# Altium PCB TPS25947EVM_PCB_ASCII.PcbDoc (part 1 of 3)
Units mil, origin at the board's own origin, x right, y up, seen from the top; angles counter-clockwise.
Board outline 6500 x 3000 mil, 4 copper layers (L1-Top Layer, L2-GND1, L3-PWR/SIG, L4-Bottom Layer), stack 63.4 mil thick; 232 components, 92 nets, 448 pads, 577 vias.
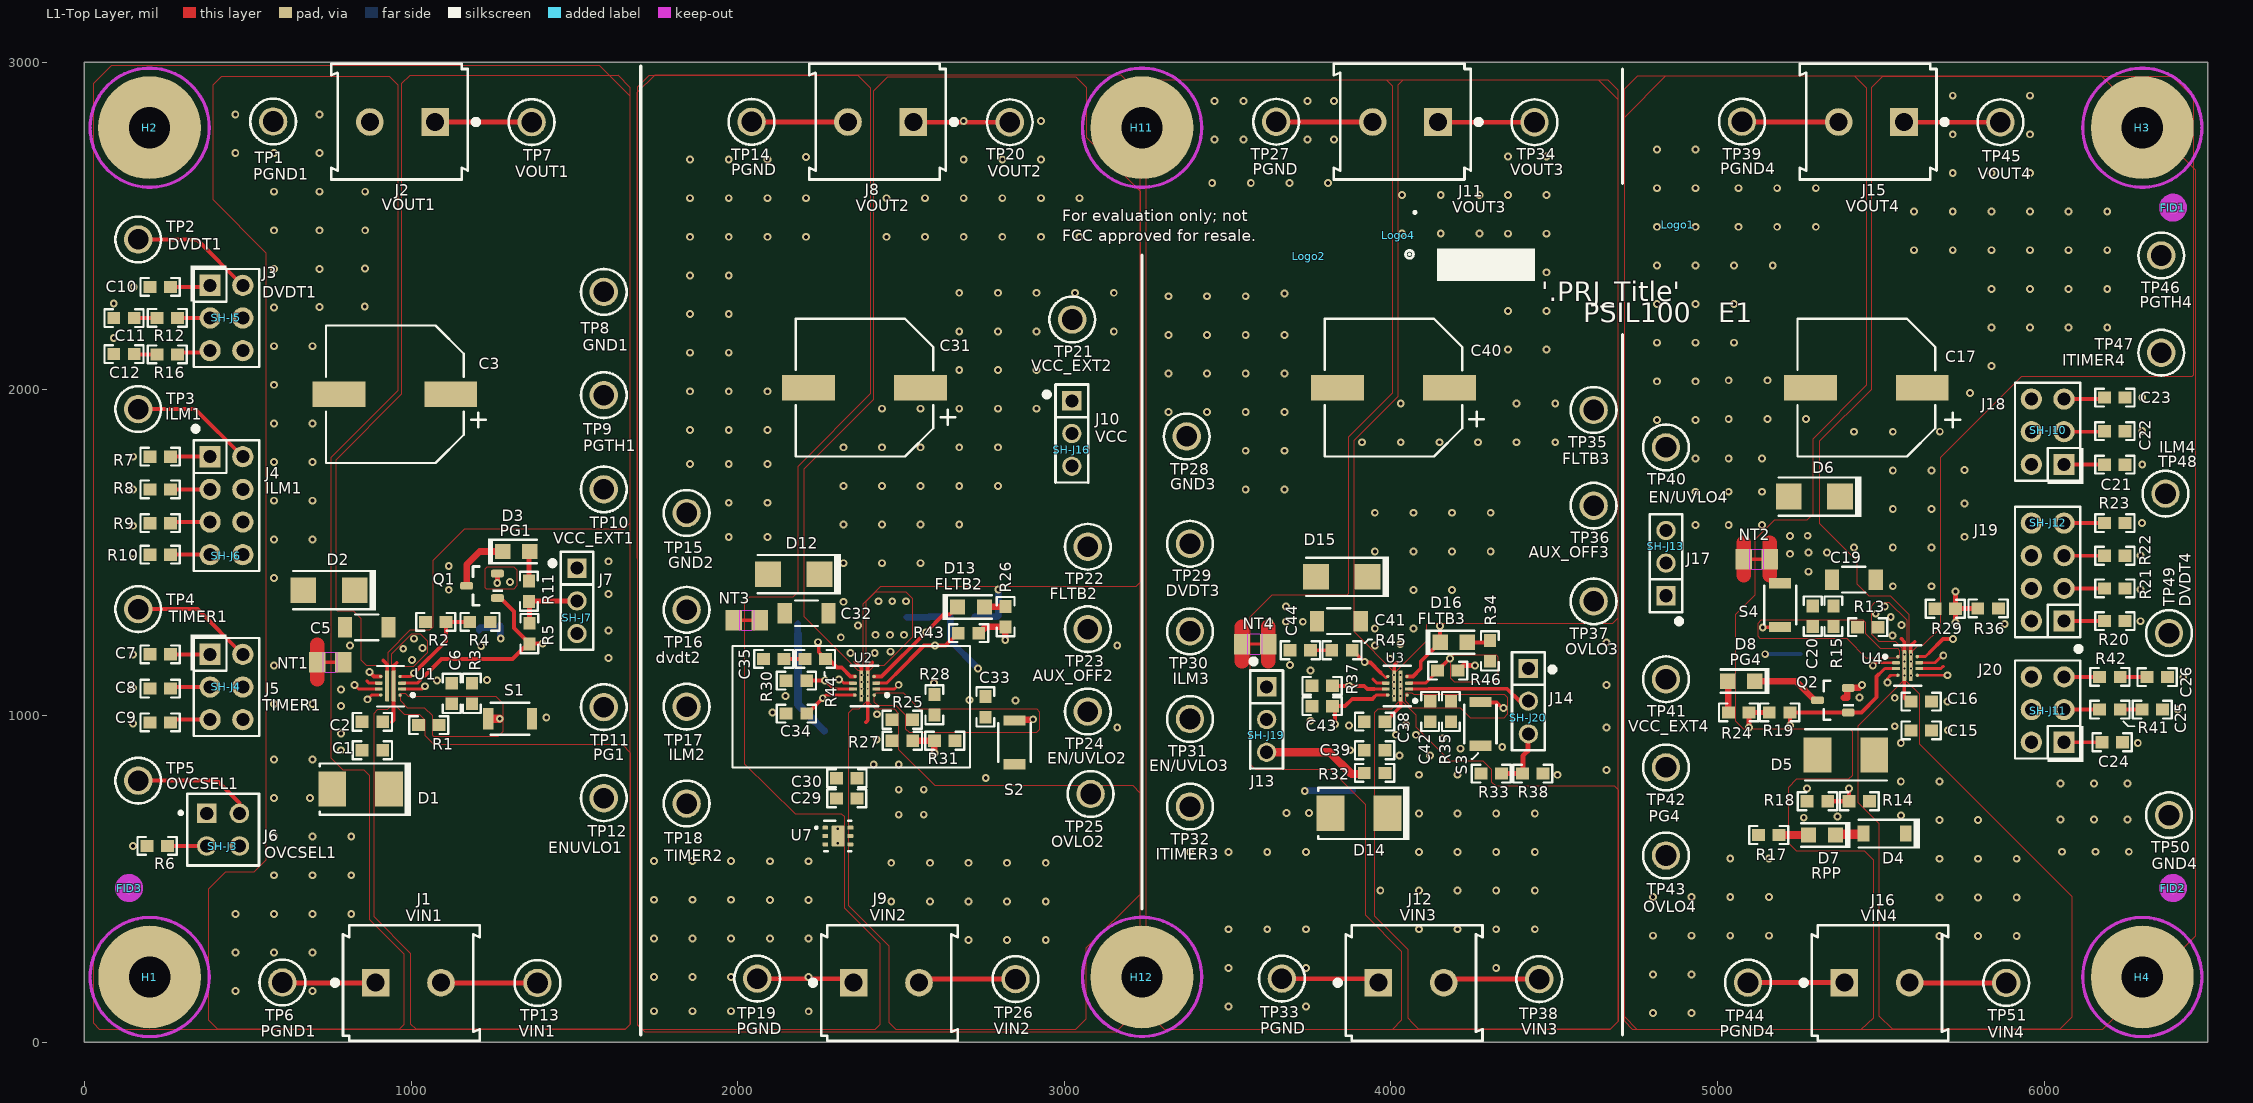
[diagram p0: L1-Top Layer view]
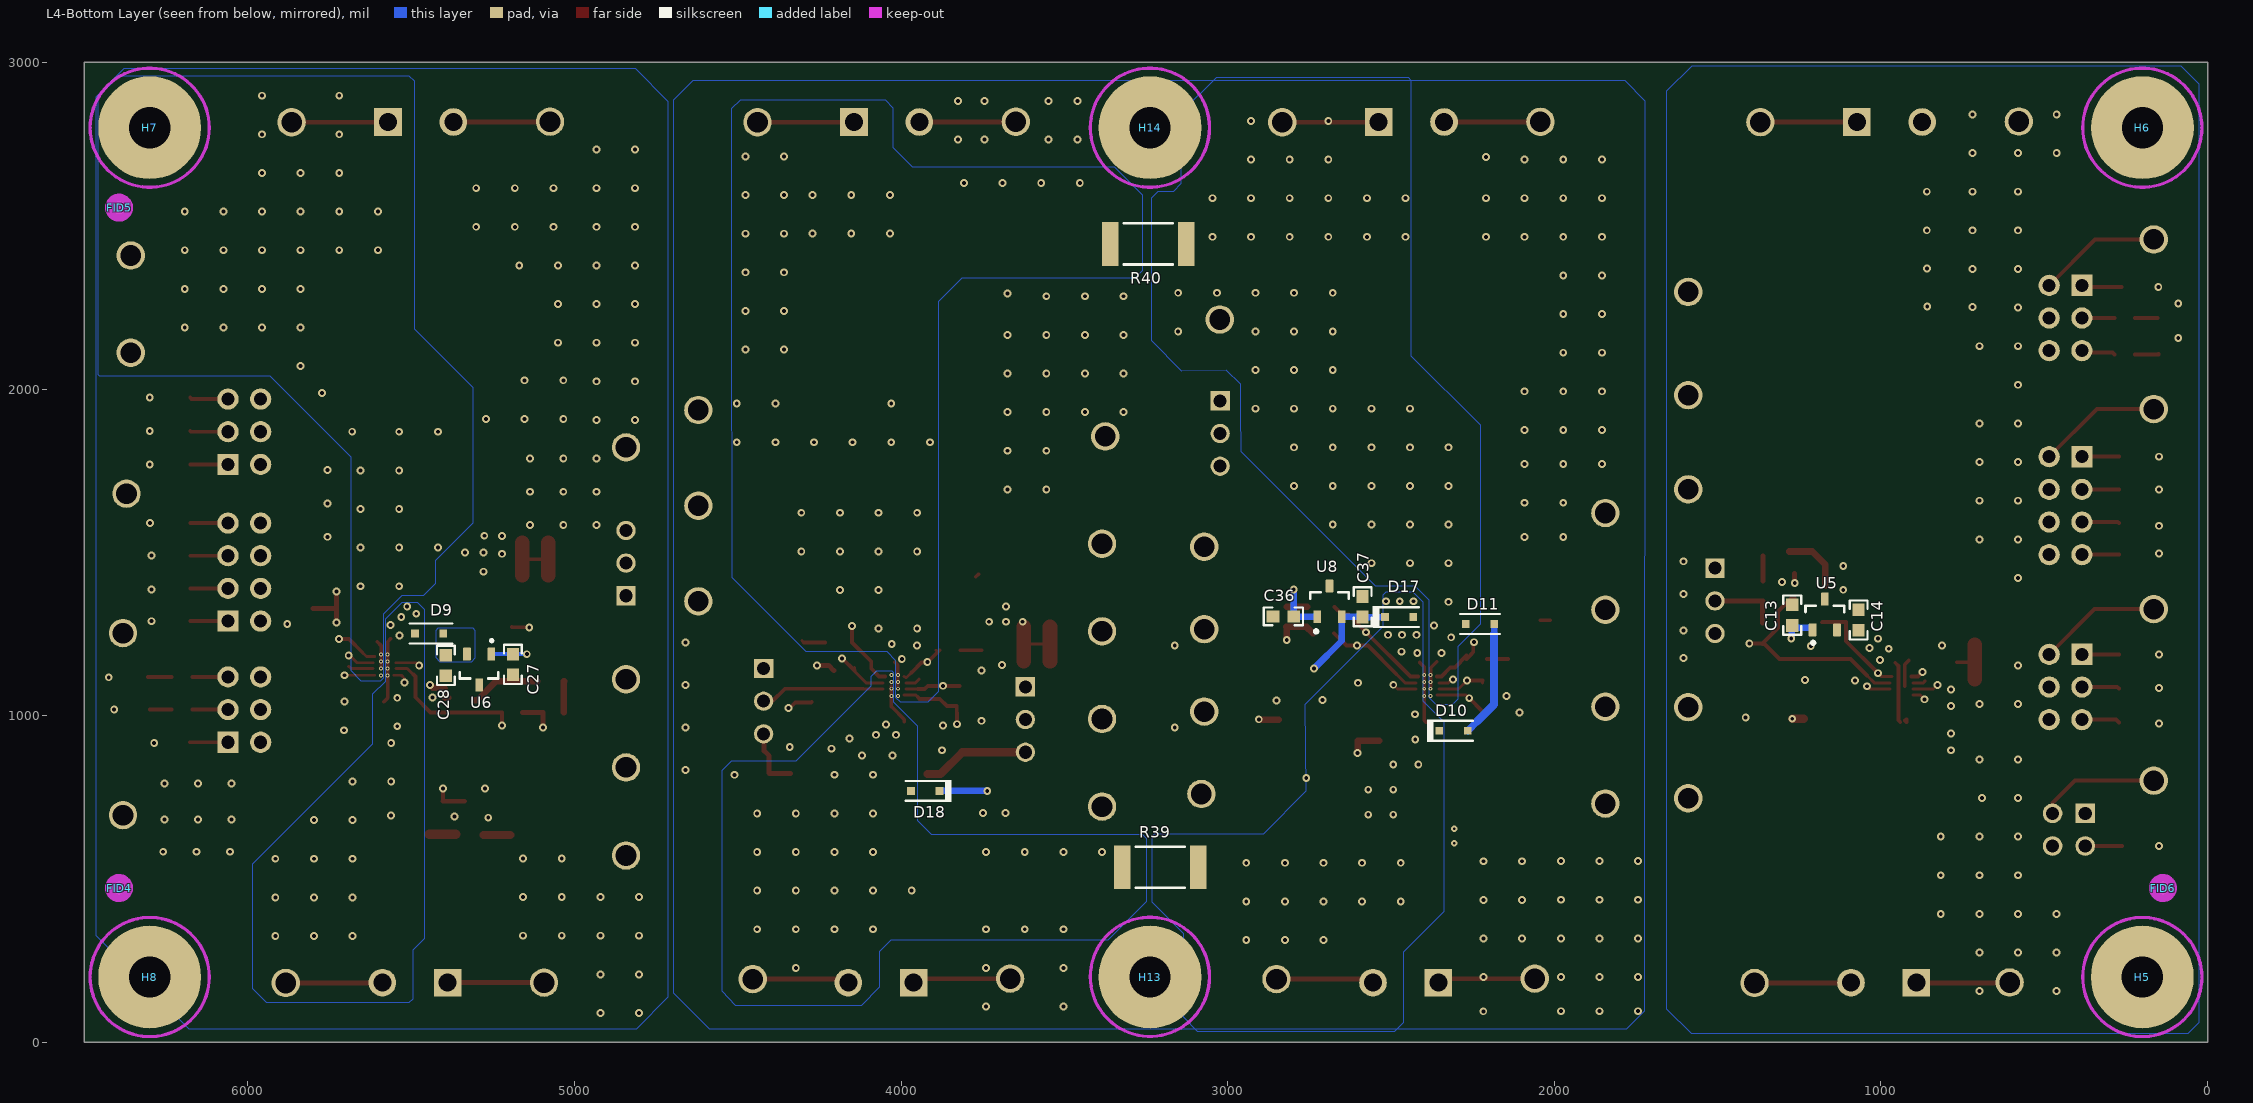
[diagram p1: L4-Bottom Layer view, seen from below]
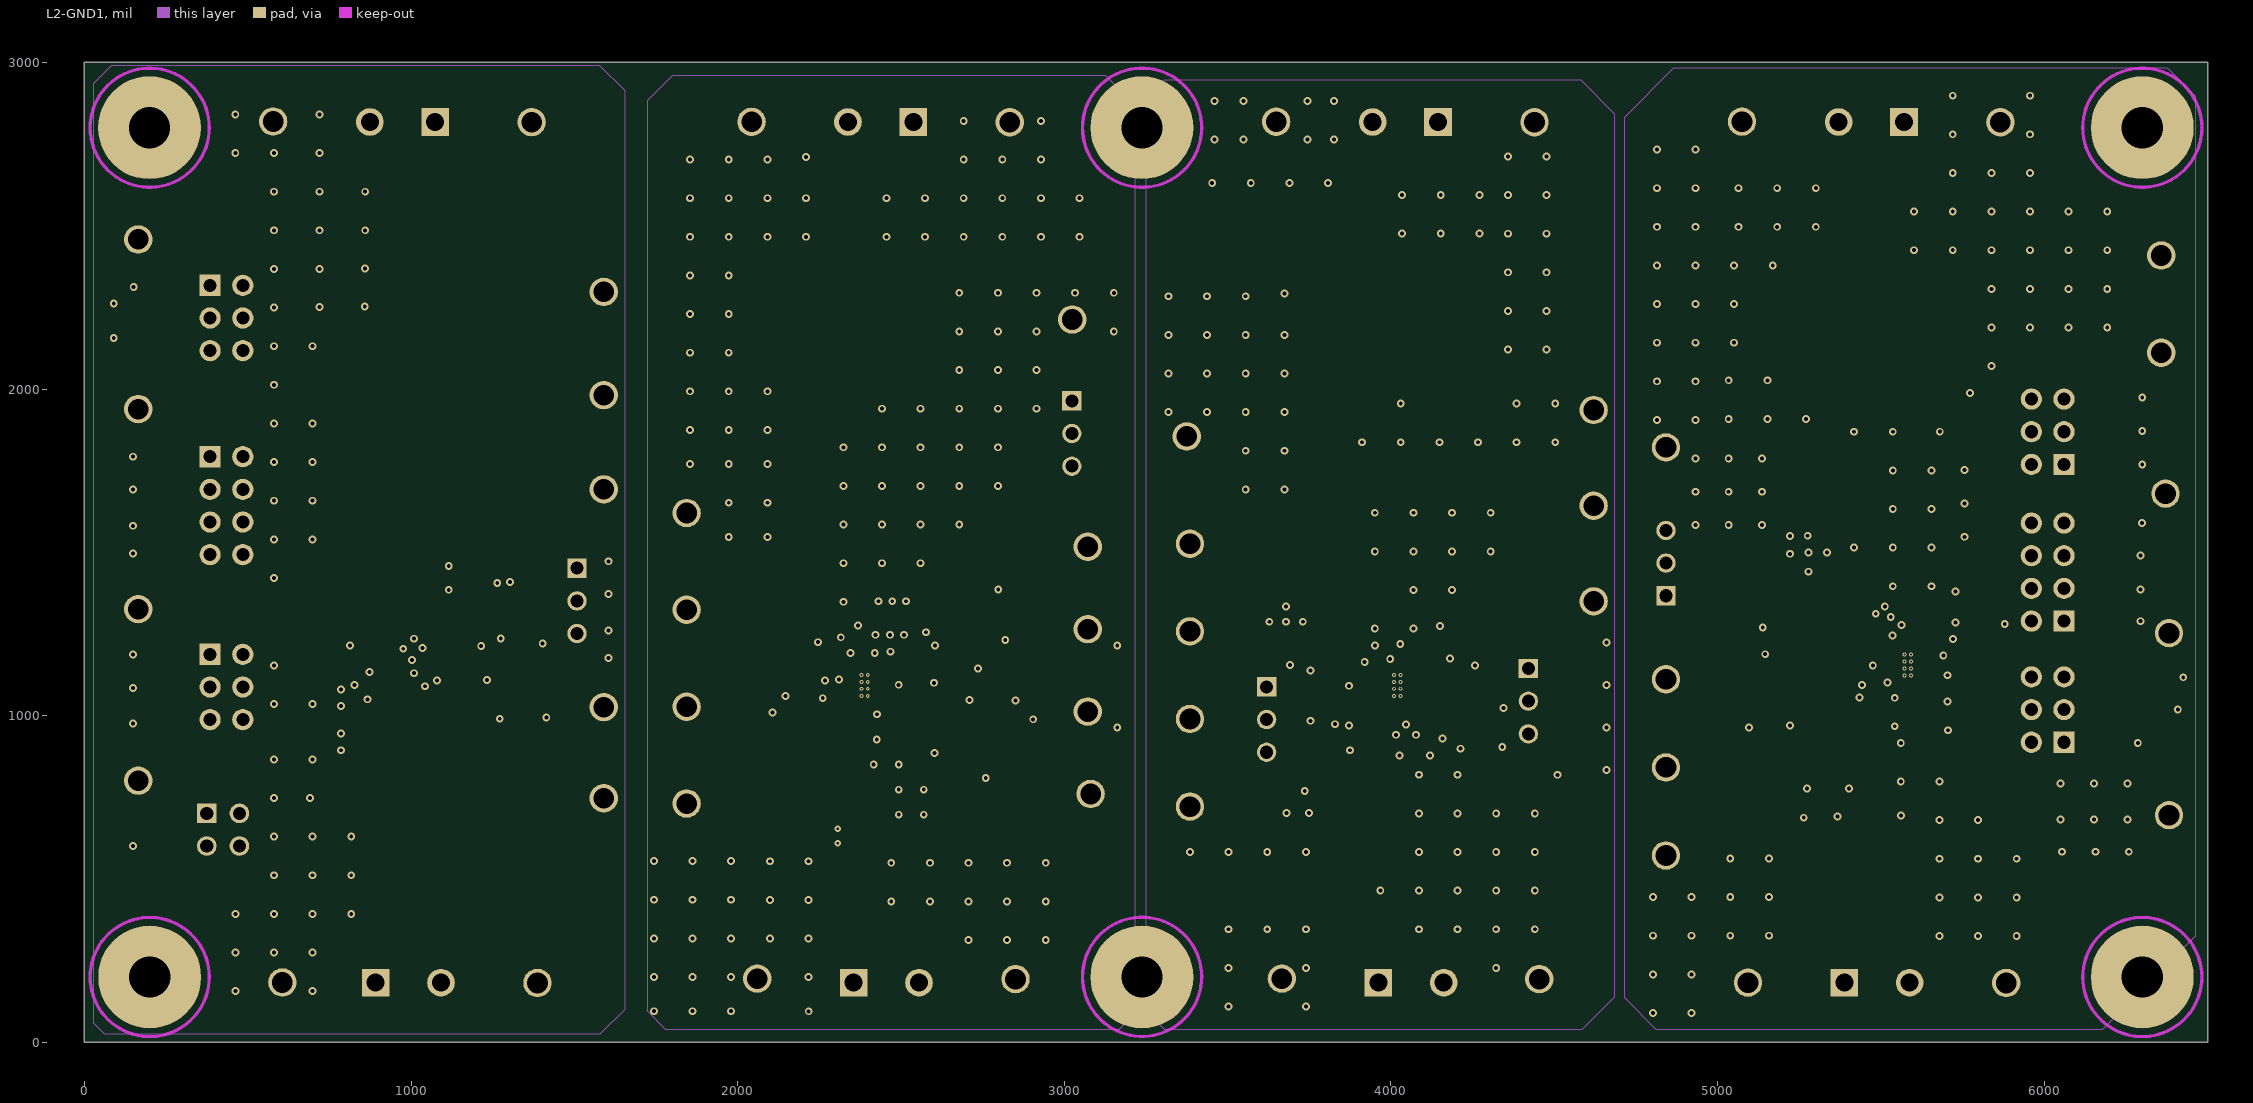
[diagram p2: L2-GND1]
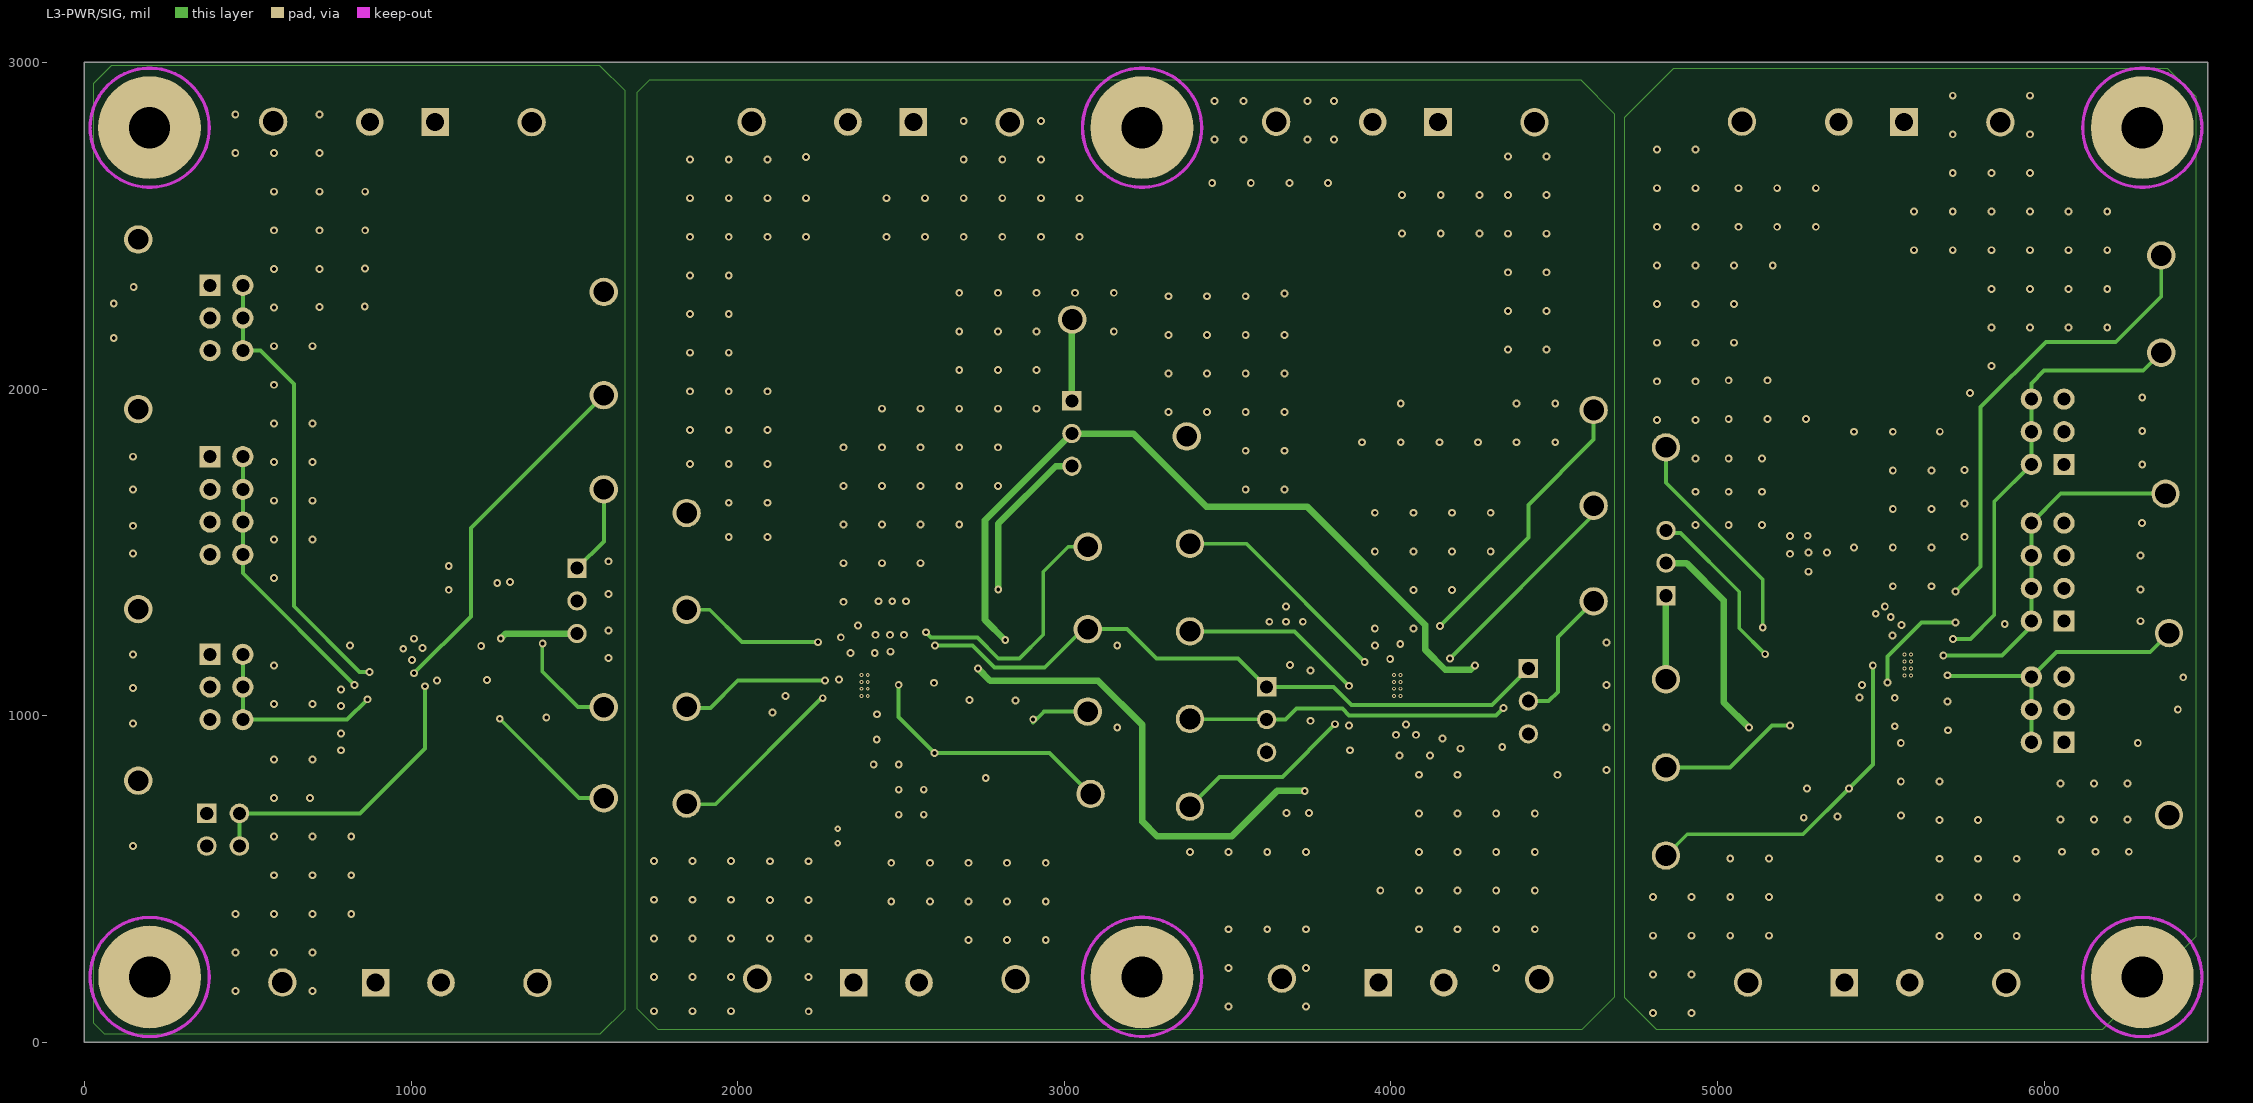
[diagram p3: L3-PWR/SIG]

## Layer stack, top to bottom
Top Solder: solder mask 0.4, Solder Resist, Dk 3.5
L1-Top Layer: signal copper 2.8
Dielectric 3: dielectric 10, FR-4 HIGH TG, Dk 4.2
L2-GND1: signal copper 1.4
Dielectric 2: dielectric 35, FR-4 HIGH TG, Dk 4.2
L3-PWR/SIG: signal copper 1.4
Dielectric1: core 10, FR-4 HIGH TG, Dk 4.2
L4-Bottom Layer: signal copper 2.8
Bottom Solder: solder mask 0.4, Solder Resist, Dk 3.5

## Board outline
0,0 6500,0 6500,3000 0,3000

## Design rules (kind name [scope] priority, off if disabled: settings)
AcuteAngle [All] p0: scope1count=1 scope1_0_kind=Board scope1_0_value=Board scope2count=1 scope2_0_kind=Board scope2_0_value=Board commentlength=0 minimum=4.50000000000000E+0001
AcuteAngle [All] p1: minimum=4.50000000000000E+0001 checktracksonly=FALSE
AssemblyTestPointUsage [All] p0: scope1count=1 scope1_0_kind=Board scope1_0_value=Board scope2count=1 scope2_0_kind=Board scope2_0_value=Board commentlength=0
AssemblyTestPointUsage [All] p1: valid=2
AssemblyTestpoint [All] p0: scope1count=1 scope1_0_kind=Board scope1_0_value=Board scope2count=1 scope2_0_kind=Board scope2_0_value=Board commentlength=0
BoardOutlineClearance [All] p0: scope1count=1 scope1_0_kind=Board scope1_0_value=Board scope2count=1 scope2_0_kind=Board scope2_0_value=Board commentlength=0 gap=40
BoardOutlineClearance [All] p1: gap=40 ignorepadtopadclearanceinfootprint=FALSE except(0: Track-OutlineEdge Text-OutlineEdge Text-CavityEdge Text-CutoutEdge Text-SplitBarrior Text-SplitContinuation)
Clearance Clearance_Poly [All] p0 off: scope1count=1 scope1_0_kind=Board scope1_0_value=Board scope2count=1 scope2_0_kind=Board scope2_0_value=Board commentlength=48 gap=15 // Protel DXP Scope 1 Expression Was: InPolygon
Clearance [All] p0: scope1count=1 scope1_0_kind=Board scope1_0_value=Board scope2count=1 scope2_0_kind=Board scope2_0_value=Board commentlength=0 gap=8
Clearance "banana jack" [All] p0: scope1count=1 scope1_0_kind=PadClass scope1_0_value="banan jack" scope2count=1 scope2_0_kind=Board scope2_0_value=Board commentlength=0 gap=25
Clearance Clearance_Keepouts [All] p0 off: scope1count=1 scope1_0_kind=Board scope1_0_value=Board scope2count=1 scope2_0_kind=Board scope2_0_value=Board commentlength=99 gap=0 // Protel DXP Scope 2 Expression Was: ((IsTrack Or IsArc) And Not InPoly) And IsFree and IsKeepOut
Clearance Clearance_Fiducialmark [All] p0 off: scope1count=1 scope1_0_kind=Board scope1_0_value=Board scope2count=1 scope2_0_kind=Board scope2_0_value=Board commentlength=81 gap=0 // Protel DXP Scope 2 Expression Was: IsPad and InComponentClass('FiducialMark')
Clearance Clearance_Fiducialmark [IsKeepOut and InComponentClass('FiducialMark') vs IsPad and InComponentClass('FiducialMark')] p1: gap=0 ignorepadtopadclearanceinfootprint=FALSE
Clearance Clearance_Keepouts [((IsTrack Or IsArc) And Not InPoly) And IsFree and IsKeepOut vs ((IsTrack Or IsArc) And Not InPoly) And IsFree and IsKeepOut] p2: gap=0 ignorepadtopadclearanceinfootprint=FALSE
Clearance "banana jack" [InPadClass('banan jack')] p3: gap=25 ignorepadtopadclearanceinfootprint=FALSE except(0: Arc-Hole Track-Hole SMDPad-Hole THPad-Hole Via-Hole Fill-Hole Poly-Hole Region-Hole Text-Hole)
Clearance [All] p4: gap=8 ignorepadtopadclearanceinfootprint=FALSE except(0: Arc-SMDPad Arc-Hole Track-Hole SMDPad-Hole THPad-Hole Via-Hole Fill-Hole Poly-Hole Region-Hole Text-Hole; 5.12: SMDPad-SMDPad; 5.8: Via-Via; 6.7: SMDPad-Via Via-Region; 6.8: Track-Via; 7.7: Track-SMDPad Track-Region; 7.87: SMDPad-Region; 10: Track-Poly THPad-THPad; 12: THPad-Poly Fill-Fill Fill-Poly; 15: Poly-Poly Poly-Region)
Clearance Clearance_Poly [InPolygon] p5: gap=15 ignorepadtopadclearanceinfootprint=FALSE except(0: Arc-SMDPad; 5.8: Via-Via; 6.7: SMDPad-Via Via-Region; 6.8: Track-Via; 10: SMDPad-Poly)
ComponentClearance [All] p0: scope1count=1 scope1_0_kind=Board scope1_0_value=Board scope2count=1 scope2_0_kind=Board scope2_0_value=Board commentlength=0 gap=10 collisioncheckmode=3
ComponentClearance ComponentClearance_THtoTH [All] p0 off: scope1count=1 scope1_0_kind=Board scope1_0_value=Board scope2count=1 scope2_0_kind=Board scope2_0_value=Board commentlength=54 gap=30 collisioncheckmode=3 // Protel DXP Scope 2 Expression Was: IsThruComponent
ComponentClearance ComponentClearance_THtoSMT [All] p0 off: scope1count=1 scope1_0_kind=Board scope1_0_value=Board scope2count=1 scope2_0_kind=Board scope2_0_value=Board commentlength=53 gap=40 collisioncheckmode=3 // Protel DXP Scope 2 Expression Was: IsSMTComponent
ComponentClearance ComponentClearance_SmallPassives [All] p0 off: scope1count=1 scope1_0_kind=Board scope1_0_value=Board scope2count=1 scope2_0_kind=Board scope2_0_value=Board commentlength=508 gap=14.96 collisioncheckmode=3 // Protel DXP Scope 2 Expression Was: HasFootprint('0201*') or HasFootprint('0402*') or HasFootprint('0508') or HasFootprint('0603*') or HasFootprint('0612') or HasFootprint('0805*') or HasFootprint('0815*') or HasFootprint('0830*') or HasFootprint('1206*') or HasFootprint('1210*') or HasFootprint('1808*') or HasFootprint('1812*') or HasFootprint('1825*') or HasFootprint('2010*') or HasFootprint('2220*') or HasFootprint('2225*') or HasFootprint('2512*') or HasFootprint('2728*') or HasFootprint('3518*')
ComponentClearance ComponentClearance_MountingHoles [All] p0: scope1count=1 scope1_0_kind=ComponentClass scope1_0_value="Mounting Holes" scope2count=1 scope2_0_kind=Board scope2_0_value=Board commentlength=0 gap=100 collisioncheckmode=3
ComponentClearance ComponentClearance_ScrewToNut [All] p0 off: scope1count=1 scope1_0_kind=Board scope1_0_value=Board scope2count=1 scope2_0_kind=Board scope2_0_value=Board commentlength=71 gap=5 collisioncheckmode=3 // Protel DXP Scope 2 Expression Was: (HasFootprint('Keystone_1902C'))
ComponentClearance ComponentClearance_Logo [All] p0: scope1count=1 scope1_0_kind=ComponentClass scope1_0_value=Logo scope2count=1 scope2_0_kind=Board scope2_0_value=Board commentlength=0 gap=0 collisioncheckmode=3
ComponentClearance ComponentClearance_Shunt [All] p0: scope1count=1 scope1_0_kind=ComponentClass scope1_0_value=Header scope2count=1 scope2_0_kind=ComponentClass scope2_0_value=Shunt commentlength=0 gap=0 collisioncheckmode=3
ComponentClearance ComponentClearance_MountingHoles_FiducialMarks [All] p0: scope1count=1 scope1_0_kind=ComponentClass scope1_0_value="Mounting Holes" scope2count=1 scope2_0_kind=ComponentClass scope2_0_value=FiducialMark commentlength=0 gap=50 collisioncheckmode=3
ComponentClearance ComponentClearance_MountingHoles_FiducialMarks [InComponentClass('Mounting Holes') vs InComponentClass('FiducialMark')] p1: gap=50 collisioncheckmode=3 verticalgap=10 showdistances=FALSE
ComponentClearance ComponentClearance_Shunt [InComponentClass('Header') vs InComponentClass('Shunt')] p2: gap=0 collisioncheckmode=3 verticalgap=0 showdistances=FALSE
ComponentClearance ComponentClearance_Logo [InComponentClass('Logo')] p3: gap=0 collisioncheckmode=3 verticalgap=0 showdistances=FALSE
ComponentClearance ComponentClearance_ScrewToNut [(HasFootprint('NY PMS 440 0025 PH')) vs (HasFootprint('Keystone_1902C'))] p4: gap=5 collisioncheckmode=3 verticalgap=10 showdistances=FALSE
ComponentClearance ComponentClearance_MountingHoles [InComponentClass('Mounting Holes')] p5: gap=100 collisioncheckmode=3 verticalgap=100000 showdistances=FALSE
ComponentClearance ComponentClearance_SmallPassives [HasFootprint('0201*') or HasFootprint('0402*') or HasFootprint('0508') or HasFootprint('0603*') or HasFootprint('0612') or HasFootprint('0805*') or HasFootprint('0815*') or HasFootprint('0830*') or HasFootprint('1206*') or HasFootprint('1210*') or HasFootprint('1808*') or HasFootprint('1812*') or HasFootprint('1825*') or HasFootprint('2010*') or HasFootprint('2220*') or HasFootprint('2225*') or HasFootprint('2512*') or HasFootprint('2728*') or HasFootprint('3518*') vs HasFootprint('0201*') or HasFootprint('0402*') or HasFootprint('0508') or HasFootprint('0603*') or HasFootprint('0612') or HasFootprint('0805*') or HasFootprint('0815*') or HasFootprint('0830*') or HasFootprint('1206*') or HasFootprint('1210*') or HasFootprint('1808*') or HasFootprint('1812*') or HasFootprint('1825*') or HasFootprint('2010*') or HasFootprint('2220*') or HasFootprint('2225*') or HasFootprint('2512*') or HasFootprint('2728*') or HasFootprint('3518*')] p6: gap=14.96 collisioncheckmode=3 verticalgap=10 showdistances=FALSE
ComponentClearance ComponentClearance_THtoSMT [IsThruComponent vs IsSMTComponent] p7: gap=40 collisioncheckmode=3 verticalgap=30 showdistances=FALSE
ComponentClearance ComponentClearance_THtoTH [IsThruComponent vs IsThruComponent] p8: gap=30 collisioncheckmode=3 verticalgap=30 showdistances=FALSE
ComponentClearance [All] p9: gap=10 collisioncheckmode=3 verticalgap=10 showdistances=FALSE
DiffPairsRouting [All] p0: scope1count=1 scope1_0_kind=Board scope1_0_value=Board scope2count=1 scope2_0_kind=Board scope2_0_value=Board commentlength=0
DiffPairsRouting [All] p1: maxlimit=100 minlimit=10 mostfreqgap=10 toplayer_minwidth=15 toplayer_maxwidth=15 toplayer_prefwidth=15 midlayer1_minwidth=15 midlayer1_maxwidth=15 midlayer1_prefwidth=15 midlayer2_minwidth=15 midlayer2_maxwidth=15 midlayer2_prefwidth=15 bottomlayer_minwidth=15 bottomlayer_maxwidth=15 bottomlayer_prefwidth=15 maxuncoupledlength=1000
FabricationTestPointUsage TestPointUsage [All] p0: scope1count=1 scope1_0_kind=Board scope1_0_value=Board scope2count=1 scope2_0_kind=Board scope2_0_value=Board commentlength=0 valid=2 allowmultiple=FALSE
FabricationTestPointUsage TestPointUsage [All] p1: valid=2 allowmultiple=FALSE
FabricationTestpoint Testpoint [All] p0: scope1count=1 scope1_0_kind=Board scope1_0_value=Board scope2count=1 scope2_0_kind=Board scope2_0_value=Board commentlength=0 side=3 testpointundercomponent=TRUE minsize=40 maxsize=100 preferedsize=60 minholesize=0 maxholesize=40 preferedholesize=32 testpointgrid=1
FabricationTestpoint Testpoint [All] p1: side=3 testpointundercomponent=TRUE minsize=40 maxsize=100 preferedsize=60 minholesize=0 maxholesize=40 preferedholesize=32 testpointgrid=1 allowsidetop=TRUE allowsidebottom=TRUE usegrid=TRUE gridtolerance=0.01
FanoutControl Fanout_Small [All] p0 off: scope1count=1 scope1_0_kind=Board scope1_0_value=Board scope2count=1 scope2_0_kind=Board scope2_0_value=Board commentlength=84 // Protel DXP Scope 1 Expression Was: (CompPinCount < 5)   Fanout_Small (Default Rule)
FanoutControl Fanout_Default [All] p0: scope1count=1 scope1_0_kind=Board scope1_0_value=Board scope2count=1 scope2_0_kind=Board scope2_0_value=Board commentlength=30 // Fanout_Default (Default Rule)
FanoutControl Fanout_SOIC [All] p0 off: scope1count=1 scope1_0_kind=Board scope1_0_value=Board scope2count=1 scope2_0_kind=Board scope2_0_value=Board commentlength=71 // Protel DXP Scope 1 Expression Was: IsSOIC   Fanout_SOIC (Default Rule)
FanoutControl Fanout_BGA [All] p0 off: scope1count=1 scope1_0_kind=Board scope1_0_value=Board scope2count=1 scope2_0_kind=Board scope2_0_value=Board commentlength=69 // Protel DXP Scope 1 Expression Was: IsBGA   Fanout_BGA (Default Rule)
FanoutControl Fanout_LCC [All] p0 off: scope1count=1 scope1_0_kind=Board scope1_0_value=Board scope2count=1 scope2_0_kind=Board scope2_0_value=Board commentlength=69 // Protel DXP Scope 1 Expression Was: IsLCC   Fanout_LCC (Default Rule)
FanoutControl Fanout_LCC [IsLCC] p1: bgadir=Out bgaviamode=Centered fanoutstyle=Auto fanoutdirection=Alternating viagrid=1 // Fanout_LCC (Default Rule)
FanoutControl Fanout_BGA [IsBGA] p2: bgadir=Out bgaviamode=Centered fanoutstyle=Auto fanoutdirection=Alternating viagrid=1 // Fanout_BGA (Default Rule)
FanoutControl Fanout_Default [All] p4: bgadir=Out bgaviamode=Centered fanoutstyle=Auto fanoutdirection=Alternating viagrid=1 // Fanout_Default (Default Rule)
FanoutControl Fanout_Small [(CompPinCount < 5)] p5: bgadir=Out bgaviamode=Centered fanoutstyle=Auto fanoutdirection=OutThenIn viagrid=1 // Fanout_Small (Default Rule)
Height [All] p0: scope1count=1 scope1_0_kind=Board scope1_0_value=Board scope2count=1 scope2_0_kind=Board scope2_0_value=Board commentlength=0
HoleSize [All] p0: scope1count=1 scope1_0_kind=Board scope1_0_value=Board scope2count=1 scope2_0_kind=Board scope2_0_value=Board commentlength=0 absolutevalues=TRUE maxlimit=251 minlimit=6 maxpercent=80.000 minpercent=20.000
HoleSize [All] p1: absolutevalues=TRUE maxlimit=251 minlimit=6 maxpercent=80.000 minpercent=20.000
HoleToHoleClearance [All] p0: scope1count=1 scope1_0_kind=Board scope1_0_value=Board scope2count=1 scope2_0_kind=Board scope2_0_value=Board commentlength=0
LayerPairs [All] p0: scope1count=1 scope1_0_kind=Board scope1_0_value=Board scope2count=1 scope2_0_kind=Board scope2_0_value=Board commentlength=0 enforce=TRUE
MinimumAnnularRing [All] p0: scope1count=1 scope1_0_kind=Board scope1_0_value=Board scope2count=1 scope2_0_kind=Board scope2_0_value=Board commentlength=0 minimumring=3
MinimumAnnularRing MinimumAnnularRing_ThermalPadVias [All] p0 off: scope1count=1 scope1_0_kind=Board scope1_0_value=Board scope2count=1 scope2_0_kind=Board scope2_0_value=Board commentlength=63 minimumring=5.91 // Protel DXP Scope 1 Expression Was: IsVia and InAnyComponent
MinimumAnnularRing MinimumAnnularRing_ThermalPadVias [IsVia and InAnyComponent] p1: minimumring=5.91
MinimumAnnularRing [All] p2: minimumring=3
MinimumSolderMaskSliver [All] p0: scope1count=1 scope1_0_kind=Board scope1_0_value=Board scope2count=1 scope2_0_kind=Board scope2_0_value=Board commentlength=0
MinimumSolderMaskSliver MinimumSolderMaskSliver_Logo [All] p0: scope1count=1 scope1_0_kind=ComponentClass scope1_0_value=Logo scope2count=1 scope2_0_kind=ComponentClass scope2_0_value=Logo commentlength=0
MinimumSolderMaskSliver MinimumSolderMaskSliver_Logo [InComponentClass('Logo') vs InComponentClass('Logo')] p1: minsoldermaskwidth=0.7
MinimumSolderMaskSliver [All] p2: minsoldermaskwidth=4
NetAntennae [All] p0: scope1count=1 scope1_0_kind=Board scope1_0_value=Board scope2count=1 scope2_0_kind=Board scope2_0_value=Board commentlength=0
PasteMaskExpansion [All] p0: scope1count=1 scope1_0_kind=Board scope1_0_value=Board scope2count=1 scope2_0_kind=Board scope2_0_value=Board commentlength=0 expansion=0
PlaneClearance [All] p0: scope1count=1 scope1_0_kind=Board scope1_0_value=Board scope2count=1 scope2_0_kind=Board scope2_0_value=Board commentlength=0 clearance=20
PlaneConnect [All] p0: scope1count=1 scope1_0_kind=Board scope1_0_value=Board scope2count=1 scope2_0_kind=Board scope2_0_value=Board commentlength=0 planeconnectstyle=Relief reliefexpansion=10 reliefentries=4 reliefconductorwidth=10 reliefairgap=10
PlaneConnect [All] p1: planeconnectstyle=Relief reliefexpansion=10 reliefentries=4 reliefconductorwidth=10 reliefairgap=10
PolygonConnect [All] p0: scope1count=1 scope1_0_kind=Board scope1_0_value=Board scope2count=1 scope2_0_kind=Board scope2_0_value=Board commentlength=0 connectstyle=Relief reliefconductorwidth=20 reliefentries=4 polygonreliefangle="90 Angle"
PolygonConnect [All] p1: thpad.connectstyle=Relief thpad.reliefconductorwidth=20 thpad.reliefentries=4 thpad.polygonreliefangle="90 Angle" thpad.airgapwidth=10 smdpad.connectstyle=Direct smdpad.reliefconductorwidth=10 smdpad.reliefentries=4 smdpad.polygonreliefangle="90 Angle" smdpad.airgapwidth=10 via.connectstyle=Direct via.reliefconductorwidth=10 via.reliefentries=4 via.polygonreliefangle="90 Angle" via.airgapwidth=10
RoutingCorners [All] p0: scope1count=1 scope1_0_kind=Board scope1_0_value=Board scope2count=1 scope2_0_kind=Board scope2_0_value=Board commentlength=0 cornerstyle=45-Degree minsetback=100 maxsetback=100
RoutingLayers [All] p0: scope1count=1 scope1_0_kind=Board scope1_0_value=Board scope2count=1 scope2_0_kind=Board scope2_0_value=Board commentlength=0 top layer=Automatic mid layer 1=Automatic mid layer 2=Automatic bottom layer=Automatic
RoutingPriority [All] p0: scope1count=1 scope1_0_kind=Board scope1_0_value=Board scope2count=1 scope2_0_kind=Board scope2_0_value=Board commentlength=0
RoutingTopology [All] p0: scope1count=1 scope1_0_kind=Board scope1_0_value=Board scope2count=1 scope2_0_kind=Board scope2_0_value=Board commentlength=0 topology=Shortest
RoutingVias [All] p0: scope1count=1 scope1_0_kind=Board scope1_0_value=Board scope2count=1 scope2_0_kind=Board scope2_0_value=Board commentlength=0 holewidth=12 width=24 viastyle="Through Hole" minholewidth=6 minwidth=12 maxholewidth=40 maxwidth=65
RoutingVias ThermalPadVias [All] p0 off: scope1count=1 scope1_0_kind=Board scope1_0_value=Board scope2count=1 scope2_0_kind=Board scope2_0_value=Board commentlength=63 holewidth=7.87 width=19.68 viastyle="Through Hole" minholewidth=6 minwidth=12 maxholewidth=12.99 maxwidth=23.62 // Protel DXP Scope 1 Expression Was: IsVia and InAnyComponent
RoutingVias ThermalPadVias [IsVia and InAnyComponent] p1: holewidth=7.87 width=19.68 viastyle="Through Hole" minholewidth=6 minwidth=12 maxholewidth=12.99 maxwidth=23.62
RoutingVias [All] p2: holewidth=12 width=24 viastyle="Through Hole" minholewidth=6 minwidth=12 maxholewidth=40 maxwidth=65
ShortCircuit [All] p0: scope1count=1 scope1_0_kind=Board scope1_0_value=Board scope2count=1 scope2_0_kind=Board scope2_0_value=Board commentlength=0 allowed=FALSE
SilkToBoardRegionClearance [All] p0 off: scope1count=1 scope1_0_kind=Board scope1_0_value=Board scope2count=1 scope2_0_kind=Board scope2_0_value=Board commentlength=130 // Protel DXP Scope 1 Expression Was: Not ((IsComment or IsDesignator) And (Hide <> 'False')) and not InRegion(1000,500,4000,800)
SilkToBoardRegionClearance [Not ((IsComment or IsDesignator) And (Hide <> 'False')) and not InRegion(1000,500,4000,800)] p1:
SilkToSilkClearance [All] p0: scope1count=1 scope1_0_kind=Board scope1_0_value=Board scope2count=1 scope2_0_kind=Board scope2_0_value=Board commentlength=0
SilkToSilkClearance SilkToSilkClearance_Pb-FreeLogo [All] p0 off: scope1count=1 scope1_0_kind=Board scope1_0_value=Board scope2count=1 scope2_0_kind=Board scope2_0_value=Board commentlength=120 // Protel DXP Scope 2 Expression Was: (HasFootprint('Pb-Free_Overlay_Medium') OR HasFootprint('Pb-Free_Overlay_Small'))
SilkToSilkClearance SilkToSilkClearance_Pb-FreeLogo [(HasFootprint('Pb-Free_Overlay_Medium') OR HasFootprint('Pb-Free_Overlay_Small')) vs (HasFootprint('Pb-Free_Overlay_Medium') OR HasFootprint('Pb-Free_Overlay_Small'))] p1: silktosilkclearance=0
SilkToSilkClearance [All] p2: silktosilkclearance=3
SilkToSolderMaskClearance "Silk to Solder Mask Opening" [All] p0: scope1count=1 scope1_0_kind=Board scope1_0_value=Board scope2count=1 scope2_0_kind=Board scope2_0_value=Board commentlength=0
SilkToSolderMaskClearance SilkToComponentPadClearance [All] p0 off: scope1count=1 scope1_0_kind=Board scope1_0_value=Board scope2count=1 scope2_0_kind=Board scope2_0_value=Board commentlength=87 // Protel DXP Scope 1 Expression Was: (IsPad or IsFill or IsRegion) and InAnycomponent
SilkToSolderMaskClearance SilkToComponentPadClearance [(IsPad or IsFill or IsRegion) and InAnycomponent] p1: minsilkscreentomaskgap=3 clearancetoexposedcopper=TRUE
SilkToSolderMaskClearance "Silk to Solder Mask Opening" [All] p2: minsilkscreentomaskgap=3 clearancetoexposedcopper=FALSE
SolderMaskExpansion [All] p0: scope1count=1 scope1_0_kind=Board scope1_0_value=Board scope2count=1 scope2_0_kind=Board scope2_0_value=Board commentlength=0 expansion=1.97
SolderMaskExpansion [All] p1: expansion=1.97
UnRoutedNet [All] p0: scope1count=1 scope1_0_kind=Board scope1_0_value=Board scope2count=1 scope2_0_kind=Board scope2_0_value=Board commentlength=0
UnpouredPolygon [All] p0: scope1count=1 scope1_0_kind=Board scope1_0_value=Board scope2count=1 scope2_0_kind=Board scope2_0_value=Board commentlength=0
Width [All] p0: scope1count=1 scope1_0_kind=Board scope1_0_value=Board scope2count=1 scope2_0_kind=Board scope2_0_value=Board commentlength=0 maxlimit=100 minlimit=8 preferedwidth=10
Width [All] p1: maxlimit=100 minlimit=8 preferedwidth=10 checkconnectedcopper=TRUE
15 further rules are at their usual default settings.

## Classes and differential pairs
component class Shunt: SH-J3 SH-J4 SH-J5 SH-J6 SH-J7 SH-J10 SH-J11 SH-J12 SH-J13 SH-J16 SH-J19 SH-J20
component class TPS25947EVM_Page2: C29 C30 C31 C32 C33 C34 C35 C36 C37 C38 C39 C40 C41 C42 C43 C44 D10 D11 D12 D13 D14 D15 D16 D17 D18 J8 J9 J10 J11 J12 J13 J14 NT3 NT4 R25 R26 R27 R28 R30 R31 R32 R33 R34 R35 R37 R38 R39 R40 R43 R44 R45 R46 S2 S3 TP14 TP15 TP16 TP17 TP18 TP19 TP20 TP21 TP22 TP23 TP24 TP25 TP26 TP27 TP28 TP29 TP30 TP31 TP32 TP33 TP34 TP35 TP36 TP37 TP38 U2 U3 U7 U8
component class TPS25947EVM_Page1: C1 C2 C3 C5 C6 C7 C8 C9 C10 C11 C12 C13 C14 C15 C16 C17 C19 C20 C21 C22 C23 C24 C25 C26 C27 C28 D1 D2 D3 D4 D5 D6 D7 D8 D9 J1 J2 J3 J4 J5 J6 J7 J15 J16 J17 J18 J19 J20 NT1 NT2 Q1 Q2 R1 R2 R3 R4 R5 R6 R7 R8 R9 R10 R11 R12 R13 R14 R15 R16 R17 R18 R19 R20 R21 R22 R23 R24 R29 R36 R41 R42 S1 S4 TP1 TP2 TP3 TP4 TP5 TP6 TP7 TP8 TP9 TP10 TP11 TP12 TP13 TP39 TP40 TP41 TP42 TP43 TP44 TP45 TP46 TP47 TP48 TP49 TP50 TP51 U1 U4 U5 U6
component class "Mounting Holes": H1 H2 H3 H4 H11 H12
component class Logo: Logo1
component class Header: J3 J4 J5 J6 J7 J10 J13 J14 J17 J18 J19 J20
component class AssemblyNote: ZZ1 ZZ2 ZZ3 ZZ4
component class FiducialMark: FID1 FID2 FID3 FID4 FID5 FID6
component class TPS25947EVM_Hardware: FID1 FID2 FID3 FID4 FID5 FID6 H1 H2 H3 H4 H5 H6 H7 H8 H11 H12 H13 H14 Logo1 Logo2 Logo4 SH-J3 SH-J4 SH-J5 SH-J6 SH-J7 SH-J10 SH-J11 SH-J12 SH-J13 SH-J16 SH-J19 SH-J20 ZZ1 ZZ2 ZZ3 ZZ4

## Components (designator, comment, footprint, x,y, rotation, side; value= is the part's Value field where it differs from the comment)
C1 "C1608X7R1V105K080AC" 0603 881.8,894.17 r180 top
C2 "GRM188R71H104KA93D" 0603 881.8,981.27 r180 top
C3 "EEE-FC1V221P" SM_RADIAL_G 950.57,1984.01 r180 top
C5 "CGA5L1X7R1H106K160AC" 1206_190 864.6,1270.3 r180 top
C6 "885012006057" 0603 1124.7,1068 r90 top
C7 "GRM188R71H221KA01D" 0603 231.93,1187.79 r180 top
C8 "C0603C222K5RAC" 0603 231.93,1082.86 r180 top
C9 "C0603X223K5RACTU" 0603 231.93,979.26 r180 top
C10 "C0603X332K5RACTU" 0603 231.93,2312.56 r180 top
C11 "GRM1885C1H103JA01D" 0603 121.3,2217.47 r180 top
C12 "C0603X223K5RACTU" 0603 121.3,2107.1 r180 top
C13 "06035C104KAT2A" 0603 1271.6,1307.99 r90 bottom
C14 "06035C104KAT2A" 0603 1068.7,1292.89 r90 bottom
C15 "C1608X7R1V105K080AC" 0603 5623,955.06 r0 top
C16 "GRM188R71H104KA93D" 0603 5623,1043.01 r0 top
C17 "EEE-FC1V221P" SM_RADIAL_G 5455.3,2004.3 r180 top
C19 "CGA5L1X7R1H106K160AC" 1206_190 5417.1,1416.6 r180 top
C20 "885012006057" 0603 5291.12,1304.79 r90 top
C21 "GRM188R71H221KA01D" 0603 6215.93,1768.4 r0 top
C22 "C0603C222K5RAC" 0603 6215.93,1871.05 r0 top
C23 "C0603X223K5RACTU" 0603 6215.93,1973.7 r0 top
C24 "C0603X332K5RACTU" 0603 6207.83,918.7 r0 top
C25 "GRM1885C1H103JA01D" 0603 6330.53,1018.83 r0 top
C26 "C0603X223K5RACTU" 0603 6345.53,1118 r0 top
C27 "06035C104KAT2A" 0603 5188.03,1156.78 r270 bottom
C28 "06035C104KAT2A" 0603 5393.49,1153.68 r270 bottom
C29 "C1608X7R1V105K080AC" 0603 2333.8,746.79 r180 top
C30 "GRM188R71H104KA93D" 0603 2334.2,808.4 r180 top
C31 "EEE-FC1V221P" SM_RADIAL_G 2388.1,2004.3 r180 top
C32 "CGA5L1X7R1H106K160AC" 1206_190 2210.8,1313.6 r180 top
C33 "885012006057" 0603 2758.33,1026.92 r90 top
C34 "C0603C222K5RAC" 0603 2179.8,1006.6 r180 top
C35 "GRM1885C1H103JA01D" 0603 2110.3,1173.87 r180 top
C36 "06035C104KAT2A" 0603 2829.3,1303.8 r0 bottom
C37 "06035C104KAT2A" 0603 2586.88,1333.54 r90 bottom
C38 "C1608X7R1V105K080AC" 0603 3949.81,981.66 r180 top
C39 "GRM188R71H104KA93D" 0603 3949.81,894.16 r180 top
C40 "EEE-FC1V221P" SM_RADIAL_G 4007.8,2004.3 r180 top
C41 "CGA5L1X7R1H106K160AC" 1206_190 3840.48,1289.32 r180 top
C42 "885012006057" 0603 4119.93,1012.8 r270 top
C43 "C0603C222K5RAC" 0603 3789.3,1029.19 r180 top
C44 "GRM1885C1H103JA01D" 0603 3722.51,1200.47 r180 top
D1 "SMBJ16A-13-F" SMB 845.6,775.4 r180 top
D2 "B330A-13-F" SMA 748.6,1384.4 r180 top
D3 "LTST-C170KGKT" LTST-C170KGKT_Green 1322,1502.6 r180 top
D4 "DDZ30D-7" SOD-123 5511.05,639.19 r180 top
D5 "SMBJ16CA" SMB-Bi 5392.32,879.85 r0 top
D6 "B330A-13-F" SMA 5296.03,1670.89 r180 top
D7 "LTST-C170KRKT" LED_LTST-C170_Red 5319.52,634.69 r0 top
D8 "LTST-C170KGKT" LTST-C170KGKT_Green 5072,1106 r0 top
D9 "BAT54WS-7-F" SOD-323 5444.48,1251.7 r0 bottom
D10 "BAT54WS-7-F" SOD-323 2308.67,954.03 r180 bottom
D11 "CDSOD323-T12SC" SOD-323-Bi 2227.5,1280.7 r180 bottom
D12 "B330A-13-F" SMA 2171.62,1433.27 r180 top
D13 "LTST-C170KRKT" LED_LTST-C170_Red 2714.26,1332.81 r180 top
D14 "SMBJ16A-13-F" SMB 3902.11,700.9 r180 top
D15 "B330A-13-F" SMA 3849.49,1425.21 r180 top
D16 "LTST-C170KRKT" LED_LTST-C170_Red 4191.66,1224.52 r180 top
D17 "BAT54WS-7-F" SOD-323 2474.91,1301.8 r180 bottom
D18 "BAT54WS-7-F" SOD-323 3925.8,769.66 r0 bottom
FID1 "Fiducial" Fiducial10-20 6394.02,2555.23 r0 top
FID2 "Fiducial" Fiducial10-20 6394.02,472.42 r0 top
FID3 "Fiducial" Fiducial10-20 136.81,472.42 r0 top
FID4 "Fiducial" Fiducial10-20 6394.02,472.42 r180 bottom
FID5 "Fiducial" Fiducial10-20 6394.02,2555.23 r180 bottom
FID6 "Fiducial" Fiducial10-20 136.81,472.42 r180 bottom
H1 "NY PMS 440 0025 PH" "NY PMS 440 0025 PH" 200,200 r0 top locked
H2 "NY PMS 440 0025 PH" "NY PMS 440 0025 PH" 199.5,2800 r0 top
H3 "NY PMS 440 0025 PH" "NY PMS 440 0025 PH" 6300,2800 r0 top
H4 "NY PMS 440 0025 PH" "NY PMS 440 0025 PH" 6300,200 r0 top
H5 "1902C" Keystone_1902C 200,200 r180 bottom locked
H6 "1902C" Keystone_1902C 200,2800 r180 bottom locked
H7 "1902C" Keystone_1902C 6300,2800 r180 bottom
H8 "1902C" Keystone_1902C 6300,200 r180 bottom
H11 "NY PMS 440 0025 PH" "NY PMS 440 0025 PH" 3237.4,2800 r0 top
H12 "NY PMS 440 0025 PH" "NY PMS 440 0025 PH" 3237.4,200 r0 top
H13 "1902C" Keystone_1902C 3237.4,200 r180 bottom locked
H14 "1902C" Keystone_1902C 3237.4,2800.5 r180 bottom locked
J1 "282841-2" TEC_282841-2 991.65,182.5 r0 top
J2 "282841-2" TEC_282841-2 974,2817.5 r180 top
J3 "PEC03DAAN" SULLINS_PEC03DAAN 434.95,2217.47 r270 top
J4 "PEC04DAAN" CONN_PEC04DAAN 434.95,1642.86 r270 top
J5 "PEC03DAAN" SULLINS_PEC03DAAN 434.95,1087.79 r270 top
J6 "PEC02DAAN" Sullins_PEC02DAAN 424.67,651.16 r0 top
J7 "Header_3x1_Launchpad" CONN_PEC03SAAN 1508.18,1351.48 r270 top
J8 "282841-2" TEC_282841-2 2437.5,2817.5 r180 top
J9 "282841-2" TEC_282841-2 2455.15,182.5 r0 top
J10 "Header_3x1_Launchpad" CONN_PEC03SAAN 3022.9,1863.8 r270 top
J11 "282841-2" TEC_282841-2 4043.85,2817.5 r180 top
J12 "282841-2" TEC_282841-2 4061.5,182.5 r0 top
J13 "Header_3x1_Launchpad" CONN_PEC03SAAN 3619.32,988.16 r270 top
J14 "Header_3x1_Launchpad" CONN_PEC03SAAN 4420.6,1044.4 r270 top
J15 "282841-2" TEC_282841-2 5470.35,2817.5 r180 top
J16 "282841-2" TEC_282841-2 5488,182.5 r0 top
J17 "Header_3x1_Launchpad" CONN_PEC03SAAN 4841.8,1467.1 r90 top
J18 "PEC03DAAN" SULLINS_PEC03DAAN 6010.33,1869.3 r90 top
J19 "PEC04DAAN" CONN_PEC04DAAN 6010.33,1439.7 r90 top
J20 "PEC03DAAN" SULLINS_PEC03DAAN 6010.33,1018.7 r90 top
Logo1 "Texas Instruments" TI_Stacked_Overlay_Small 4877.73,2502.39 r0 top
Logo2 "CE Mark" CE_Mark_5mm 3748.89,2407.02 r0 top
Logo4 "WEEE logo" WEEE_Minimum 4022.6,2470.6 r0 top
NT1 "Net-Tie" Net-Tie_0805_HV_NoOverlay 752.8,1163.8 r0 top net-tie
NT2 "Net-Tie" Net-Tie_0805_HV_NoOverlay 5119.9,1479.2 r0 top net-tie
NT3 "Net-Tie" Net-Tie_0805_HV_NoOverlay 2028,1292.4 r0 top net-tie
NT4 "Net-Tie" Net-Tie_0805_HV_NoOverlay 3583.84,1219.32 r0 top net-tie
Q1 "2N7002" SOT-23 1217.21,1397.68 r180 top
Q2 "2N7002" SOT-23 5352.74,1047.26 r180 top
R1 "RC0603FR-071ML" 0603 1054.34,971.2 r180 top
R2 "RC0603FR-071ML" 0603 1075.55,1287.12 r180 top
R3 "CRCW0603124KFKEA" 0603 1186.4,1068 r270 top
R4 "CRCW0603124KFKEA" 0603 1211.17,1287.11 r180 top
R5 "RG1608P-103-B-T5" 0603 1362.32,1251.48 r90 top
R6 "RC0603FR-07392KL" 0603 222.67,601.16 r0 top
R7 "RC0603FR-076K65L" 0603 231.93,1792.86 r0 top
R8 "RC0603FR-071K65L" 0603 231.93,1692.86 r0 top
R9 "RC0603FR-07750RL" 0603 231.93,1589.24 r0 top
R10 "RC0603FR-07549RL" 0603 231.93,1492.86 r0 top
R11 "RC0603FR-071KL" 0603 1361.06,1381.01 r270 top
R12 "RC0603FR-07100RL" 0603 253.58,2217.47 r0 top
R13 "RC0603FR-072ML" 0603 5459.4,1270.9 r0 top
R14 "RC0603FR-072ML" 0603 5433.52,738.02 r0 top
R15 "RC0603FR-07249KL" 0603 5354.32,1304.83 r270 top
R16 "RC0603FR-07100RL" 0603 253.58,2105.95 r0 top
R17 "RC0603FR-07887RL" 0603 5156.32,634.69 r0 top
R18 "RC0603FR-07158KL" 0603 5305.42,738.02 r0 top
R19 "RG1608P-103-B-T5" 0603 5189.7,1010.1 r180 top
R20 "RC0603FR-076K65L" 0603 6215.93,1289.7 r180 top
R21 "RC0603FR-071K65L" 0603 6215.93,1389.7 r180 top
R22 "RC0603FR-07750RL" 0603 6215.93,1489.7 r180 top
R23 "RC0603FR-07549RL" 0603 6215.93,1589.7 r180 top
R24 "RC0603FR-071KL" 0603 5064.4,1010 r0 top
R25 "RC0603FR-071ML" 0603 2503.45,987.67 r180 top
R26 "RC0603FR-071KL" 0603 2820.06,1303.21 r270 top
R27 "RC0603FR-071ML" 0603 2504.25,923.23 r180 top
R28 "CRCW0603124KFKEA" 0603 2602.26,1033.5 r270 top
R29 "RC0603FR-071ML" 0603 5696.8,1327.4 r180 top
R30 "RC0603FR-07549RL" 0603 2179.8,1107.2 r0 top
R31 "RC0603FR-0757K6L" 0603 2633.8,923.23 r180 top
R32 "RC0603FR-071ML" 0603 3949.81,824.9 r0 top
R33 "RC0603FR-071ML" 0603 4307.03,822.6 r180 top
R34 "RC0603FR-071KL" 0603 4303.03,1198.2 r270 top
R35 "CRCW0603124KFKEA" 0603 4183.73,1012.8 r90 top
R36 "CRCW0603124KFKEA" 0603 5827.8,1328.4 r180 top
R37 "RC0603FR-07549RL" 0603 3789.3,1091.4 r0 top
R38 "RC0603FR-0778K7L" 0603 4434,822.8 r180 top
R39 "RC6432J000CS" 2512 3206.2,535.92 r0 bottom
R40 "RC6432J000CS" 2512 3243.2,2444.2 r0 bottom
R41 "RC0603FR-07100RL" 0603 6200.93,1018.9 r180 top
R42 "RC0603FR-07100RL" 0603 6200.93,1118.7 r180 top
R43 "RC0603FR-07100KL" 0603 2706.68,1252.45 r0 top
R44 "RC0603FR-07100RL" 0603 2237.8,1173.8 r0 top
R45 "RC0603FR-07100RL" 0603 3850,1200.4 r0 top
R46 "RC0603FR-07100KL" 0603 4173.9,1138 r0 top
S1 "B3U-1000P" SW_B3U-1000P 1303.49,990.66 r180 top
S2 "B3U-1000P" SW_B3U-1000P 2847.38,918.11 r90 top
S3 "B3U-1000P" SW_B3U-1000P 4273.7,974.9 r90 top
S4 "B3U-1000P" SW_B3U-1000P 5191.39,1338.48 r270 top
SH-J3 "SPC02SYAN" SPC02SYAN 424.3,600.6 r0 top
SH-J4 "SPC02SYAN" SPC02SYAN 434.97,1088.29 r0 top
SH-J5 "SPC02SYAN" SPC02SYAN 434.44,2217.47 r0 top
SH-J6 "SPC02SYAN" SPC02SYAN 434.9,1489.8 r0 top
SH-J7 "SPC02SYAN" SPC02SYAN 1508.63,1299.37 r270 top
SH-J10 "SPC02SYAN" SPC02SYAN 6012.2,1873.9 r0 top
SH-J11 "SPC02SYAN" SPC02SYAN 6011.6,1015.3 r0 top
SH-J12 "SPC02SYAN" SPC02SYAN 6012.1,1590.3 r0 top
SH-J13 "SPC02SYAN" SPC02SYAN 4841.5,1518.2 r270 top
SH-J16 "SPC02SYAN" SPC02SYAN 3022.9,1814.5 r270 top
SH-J19 "SPC02SYAN" SPC02SYAN 3618.43,939.93 r270 top
SH-J20 "SPC02SYAN" SPC02SYAN 4420.1,994 r270 top
TP1 "PGND1" Keystone5011 577.8,2819 r270 top
TP2 "dVdt1" Keystone5012 164.8,2457.9 r90 top
TP3 "ILM1" Keystone5012 164.8,1938.7 r0 top
TP4 "ITIMER1" Keystone5012 164.8,1326.3 r0 top
TP5 "OVCSEL1" Keystone5012 164.8,801.16 r0 top
TP6 "PGND1" Keystone5011 606.2,183.25 r90 top
TP7 "VOUT1" Keystone5010 1369.08,2817.13 r90 top
TP8 "GND1" Keystone5011 1590.2,2297.3 r0 top
TP9 "PGTH1" Keystone5012 1590.2,1981.35 r0 top
TP10 "VCC_EXT1" Keystone5013 1590.2,1692.86 r90 top
TP11 "PG1" Keystone5012 1590.2,1026.21 r0 top
TP12 "EN/UVLO1" Keystone5012 1590.2,747.38 r90 top
TP13 "VIN1" Keystone5010 1387.1,181.75 r270 top
TP14 "PGND" Keystone5011 2042.42,2817.87 r90 top
TP15 "GND2" Keystone5011 1843.6,1620.43 r0 top
TP16 "dVdt2" Keystone5012 1843.6,1324.2 r0 top
TP17 "ILM2" Keystone5012 1843.6,1027.6 r0 top
TP18 "ITIMER2" Keystone5012 1843.6,731 r0 top
TP19 "PGND" Keystone5011 2059.7,195.15 r90 top
TP20 "VOUT2" Keystone5010 2832.95,2816.75 r90 top
TP21 "VCC_EXT2" Keystone5013 3024.1,2212.8 r0 top
TP22 "FLTb2" Keystone5012 3071.9,1517.2 r0 top
TP23 "AUX_OFF2" Keystone5012 3071.9,1264.91 r0 top
TP24 "EN/UVLO2" Keystone5012 3071.9,1012.63 r0 top
TP25 "OVLO2" Keystone5012 3080.36,760.35 r0 top
TP26 "VIN2" Keystone5010 2850.6,193.65 r90 top
TP27 "PGND" Keystone5011 3648.4,2818.25 r90 top
TP28 "GND3" Keystone5011 3374.72,1854.89 r0 top
TP29 "dVdt3" Keystone5012 3384.6,1526.27 r0 top
TP30 "ILM3" Keystone5012 3384.6,1258.1 r0 top
TP31 "EN/UVLO3" Keystone5012 3384.6,989.93 r0 top
TP32 "ITIMER3" Keystone5012 3384.6,721.77 r0 top
TP33 "PGND" Keystone5011 3666.05,195.15 r90 top
TP34 "VOUT3" Keystone5010 4439.3,2816.75 r90 top
TP35 "FLTb3" Keystone5012 4620.3,1935.8 r0 top
TP36 "AUX_OFF3" Keystone5012 4620.3,1642.9 r0 top
TP37 "OVLO3" Keystone5012 4620.3,1350 r90 top
TP38 "VIN3" Keystone5010 4453.78,193.65 r90 top
TP39 "PGND4" Keystone5011 5074.52,2818.62 r90 top
TP40 "EN/UVLO4" Keystone5012 4841.8,1821.31 r0 top
TP41 "VCC_EXT4" Keystone5013 4841.8,1111.62 r0 top
TP42 "PG4" Keystone5012 4841.8,841.6 r0 top
TP43 "OVLO4" Keystone5012 4841.8,571.91 r90 top
TP44 "PGND4" Keystone5011 5092.92,182.87 r270 top
TP45 "VOUT4" Keystone5010 5865.8,2816.75 r90 top
TP46 "PGTH4" Keystone5012 6358.1,2408.91 r90 top
TP47 "ITIMER4" Keystone5012 6358.1,2111.3 r0 top
TP48 "ILM4" Keystone5012 6371.1,1679.8 r0 top
TP49 "dVdt4" Keystone5012 6381.8,1252.9 r0 top
TP50 "GND4" Keystone5011 6381.8,695.51 r180 top
TP51 "VIN4" Keystone5010 5883.45,181.75 r90 top
U1 "TPS259472ARPWT" RPW0010A-MFG 936.77,1090.72 r180 top
U2 "TPS259470LRPWT" RPW0010A-MFG 2388.33,1090.59 r180 top
U3 "TPS259470LRPWT" RPW0010A-MFG 4019.73,1090.72 r180 top
U4 "TPS259474LRPWT" RPW0010A-MFG 5581.47,1153.24 r0 top
U5 "LM3480IM3-3.3/NOPB" DBZ0003A_N 1171.9,1309.59 r90 bottom
U6 "LM3480IM3-3.3/NOPB" DBZ0003A_N 5291.53,1141.38 r270 bottom
U7 "TVS2200DRVR" DRV0006A 2306.7,631.6 r0 top
U8 "LM3480IM3-3.3/NOPB" DBZ0003A_N 2688.2,1350 r90 bottom
ZZ1 "This Assembly Note is for PCB labels only" AssemblyNoteLabel 308,3725.4 r0 top
ZZ2 "These assemblies are ESD sensitive, ESD precautions shall be observed." AssemblyNote 309.77,3636.62 r0 top
ZZ3 "These assemblies must be clean and free from flux and all contaminants. Use of no clean flux is not acceptable." AssemblyNote 309.77,3548.06 r0 top
ZZ4 "These assemblies must comply with workmanship standards IPC-A-610 Class 2, unless otherwise specified." AssemblyNote 309.77,3459.51 r0 top

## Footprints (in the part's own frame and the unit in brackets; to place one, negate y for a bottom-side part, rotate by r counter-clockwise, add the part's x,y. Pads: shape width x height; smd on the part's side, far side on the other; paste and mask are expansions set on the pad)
0603 [mm] "0603 from SM-752 data"
  rect 1x0.95 smd: 1(-0.8,0) 2(0.8,0)
  silkscreen extent -1.52,-0.69 1.52,0.69
1206_190 [mm] "1206_190"
  rect 1.1x1.6 smd: 1(-1.7,0) 2(1.7,0)
  silkscreen extent -0.9,-1 0.9,1
2512 [mm] "Chip Resistor, Body 6.3x3.2mm, IPC Medium Density"
  rect 1.3x3.4 smd: 1(-2.95,0) 2(2.95,0)
  silkscreen extent -1.9,-1.6 1.9,1.6
AssemblyNote [mil] "Assembly Note"
AssemblyNoteLabel [mil] "Assembly Note for PCB Labels"
CE_Mark_5mm [mil] "Minimum text height for CE Mark"
CONN_PEC03SAAN [mm] "SULLINS"
  rect 1.5x1.5 hole 1.016: 1(-2.54,0)
  round 1.5 hole 1.016: 2(0,0) 3(2.54,0)
  silkscreen extent -3.81,-2.11 3.81,1.27
CONN_PEC04DAAN [mm] "SULLINS"
  rect 1.65x1.65 hole 1.016 mask+0: 1(-3.81,-1.27)
  round 1.65 hole 1.016 mask+0: 2(-3.81,1.27) 3(-1.27,-1.27) 4(-1.27,1.27) 5(1.27,-1.27) 6(1.27,1.27) 7(3.81,-1.27) 8(3.81,1.27)
  silkscreen extent -6.18,-2.6 5.08,2.54
DBZ0003A_N [mm] "SOT23, 3-Leads, Body 2.9x1.3mm, Pitch 0.95mm, Lead Span 2.4mm, IPC Medium Density"
  rrect17% 1x0.6 smd: 1(-1.2,0.95) 2(-1.2,-0.95) 3(1.2,0)
  silkscreen extent 0.2,-1.5 0.7,1.5
DRV0006A [mm] "SON, 6-Leads, Body 2x2mm, Pitch 0.65mm, Thermal Pad 1.6x1mm, TI Recommended"
  rrect33% 0.45x0.3 smd: 1(-0.975,0.65) 2(-0.975,0) 3(-0.975,-0.65) 4(0.975,-0.65) 5(0.975,0) 6(0.975,0.65)
  rrect14% 1x0.7 on Top Paste: 7(0,-0.45) 7(0,0.45)
  rrect10% 1x1.6 smd paste-0.5: 7(0,0)
  silkscreen extent -1.05,-1.2 1.05,1.2
Fiducial10-20 [mm]
  round 1 smd mask+0: 1(0,0)
  L1-Top Layer keep-out circle w1.178: c0,0 r0.5
Keystone5010 [mil] "Keystone Multipurpose loops"
  round 87 hole 63: 1(0,0)
  silkscreen extent -70,-70 70,70
Keystone5011 [mil] "Keystone Multipurpose loops"
  round 87 hole 63: 1(0,0)
  silkscreen extent -70,-70 70,70
Keystone5012 [mil] "Keystone Multipurpose loops"
  round 87 hole 63: 1(0,0)
  silkscreen extent -70,-70 70,70
Keystone5013 [mil] "Keystone Multipurpose loops"
  round 87 hole 63: 1(0,0)
  silkscreen extent -70,-70 70,70
Keystone_1902C [mil] "Hex Standoff, 4-40 threaded, nylon"
  round 1 on Mech4: 0(0,0)
LED_LTST-C170_Red [mm] "LITE-ON"
  rect 1.2x1.2 smd: 1(-1.05,0) 2(1.05,0)
  silkscreen extent -1.6,-1 2.2,1
LTST-C170KGKT_Green [mm] "LITE-ON"
  rect 1.2x1.2 smd: 1(-1.05,0) 2(1.05,0)
  silkscreen extent -1.6,-1 2.2,1
Net-Tie_0805_HV_NoOverlay [mil] "0805_HV pads tied by 10mil copper trace which can be cut.  An 0805 part can be placed on pads."
  rect 50x63 smd paste-25: 1(-40,0) 2(40,0)
  L1-Top Layer lines w10: -16,0 16,0
  L1-Top Layer keep-out lines w1: -22,-30.91 -22,30.91 ; -14.96,-30.91 14.96,-30.91 ; -14.96,30.91 14.96,30.91 ; 22,-30.91 22,30.91
"NY PMS 440 0025 PH" [mm] "4-40 nylon screw and mounting hole"
  round 8 hole 3.2: 1(0,0)
RPW0010A-MFG [mm]
  round 0.27 smd paste-1000 mask+0: 1(-0.75,0.7) 10(0.75,0.7)
  rrect40% 0.6x0.25 smd paste+0 mask+0: 2(-0.9,0.225) 3(-0.9,-0.225) 8(0.9,-0.225) 9(0.9,0.225)
  round 0.255 smd paste-1000 mask+0: 4(-0.75,-0.75) 7(0.75,-0.75)
  rrect33% 0.3x2.4 smd paste-1000 mask+0: 5(-0.25,0) 6(0.25,0)
  silkscreen extent -1.88,-1.58 1.05,1.58
SM_RADIAL_G [mm] "10 x 10.2mm:  Panasonic G"
  rect 4.1x2 smd: 1(-4.35,0) 2(4.35,0)
  silkscreen extent -5.35,-5.35 5.35,5.35
SMA [mm] "Molded Diode, 2-Leads, Body 4.3x2.6mm, IPC Medium Density, based on OnSemi component dimensions and land pattern"
  rect 2x2 smd: 1(-2,0) 2(2,0)
  silkscreen extent -3.66,-1.57 2.79,1.57
SMB [mil] "Molded Diode, 2-Leads, Body 5.4x3.6mm, IPC Medium Density, based on OnSemi component dimensions"
  rect 85x107.99 smd: 1(-87.01,0) 2(87.01,0)
  silkscreen extent -155,-82 125,82
SMB-Bi [mil] "Molded Diode, 2-Leads, Body 5.4x3.6mm, IPC Medium Density, based on OnSemi component dimensions"
  rect 85x107.99 smd: 1(-87.01,0) 2(87.01,0)
  silkscreen extent -125,-79 125,79
SOD-123 [mm] "On Semi recommended land pattern"
  rect 0.915x1.22 smd: 1(-1.637,0) 2(1.637,0)
  silkscreen extent -2.74,-1.17 2.03,1.17
SOD-323 [mm] "NXP recommended land pattern"
  rect 0.6x0.6 smd paste-0.05: 1(-1.1,0) 2(1.1,0)
  silkscreen extent -1.8,-0.77 1.53,0.77
SOD-323-Bi [mm] "SOD323, 2-Leads, Body 1.9x1.45mm, No Polarity Mark"
  rect 0.6x0.6 smd paste-0.05: 1(-1.1,0) 2(1.1,0)
  silkscreen extent -1.53,-0.77 1.53,0.77
SOT-23 [mm] "SOT23, 3-Leads, Body 2.9x1.3mm, Pitch 0.95mm, Lead Span 2.5mm, IPC Medium Density"
  rrect50% 1x0.6 smd: 1(-1.2,0.95) 2(-1.2,-0.95) 3(1.2,0)
  silkscreen extent -1.62,-1.5 0.7,1.5
SPC02SYAN [mil] "SULLINS"
  round 1 on Mech3: 0(0,0)
Sullins_PEC02DAAN [mil] "Sullins Connector Solutions"
  rect 60x60 hole 40: 1(-50,50)
  round 60 hole 40: 2(50,50) 3(-50,-50) 4(50,-50)
  silkscreen extent -134,-110 110,110
SULLINS_PEC03DAAN [mm] "SULLINS"
  rect 1.65x1.65 hole 1.016 mask+0: 1(-2.54,-1.27)
  round 1.65 hole 1.016 mask+0: 2(-2.54,1.27) 3(0,-1.27) 4(0,1.27) 5(2.54,-1.27) 6(2.54,1.27)
  silkscreen extent -4.06,-2.79 3.81,2.54
SW_B3U-1000P [mm] "OMRON"
  rect 0.8x1.7 smd: 1(-1.7,0) 2(1.7,0)
  silkscreen extent -1.5,-1.25 1.5,1.25
TEC_282841-2 [mm] "TE Connectivity"
  rect 2.15x2.15 hole 1.4: 1(-2.54,0)
  round 2.15 hole 1.4: 2(2.54,0)
  silkscreen extent -5.9,-4.52 5.55,4.47
TI_Stacked_Overlay_Small [mil]
WEEE_Minimum [mil] "WEEElie bin"
  silkscreen extent 22,-71 54,74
